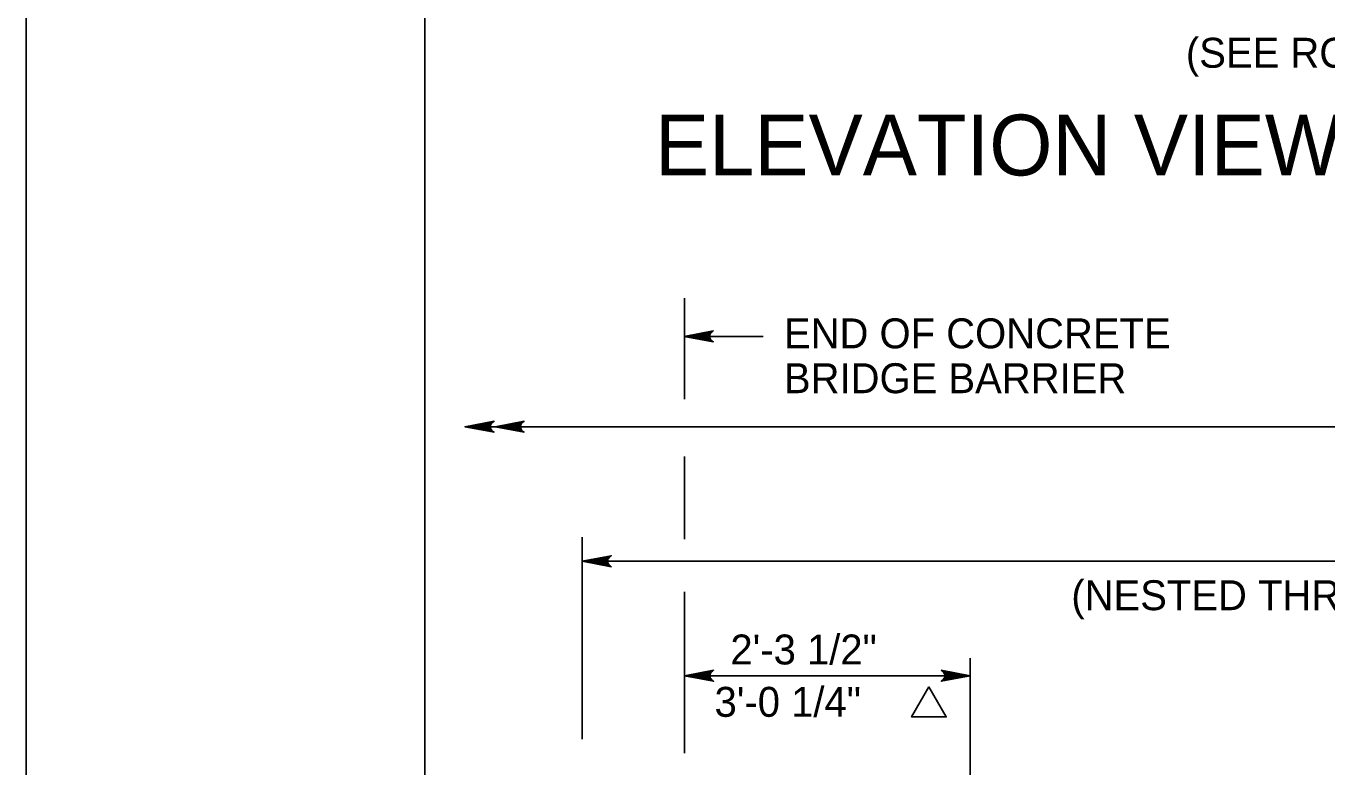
# Model space of a CAD drawing. Extents: x 632007860 to 635435983, y 295418622 to 297794622.
# Drawn here: x 632007860 to 632138300, y 297394420 to 297468725 of the extents above; entities that cross this region are included whole.
import ezdxf

# ---------------------------------------------------------------- set-up
doc = ezdxf.new("R2010")
doc.units = 0
for name, color, linetype in [('1', 7, 'Continuous'), ('2', 7, 'Continuous'), ('PLT-BNDY', 7, 'Continuous'), ('S-DETL-DIMS', 7, 'Continuous'), ('S-DETL-T120', 7, 'Continuous'), ('S-DETL-T175', 7, 'Continuous')]:
    doc.layers.add(name, color=color, linetype=linetype)

msp = doc.modelspace()

# ---------------------------------------------------------------- linework, layer by layer
at = {"layer": '1'}
msp.add_lwpolyline([(632833860, 297215622), (632833860, 297779622), (632047860, 297779622), (632047860, 297215622), (632833860, 297215622), (632833860, 297241981), (632633860, 297241981), (632633860, 297306659), (632833860, 297306659), (632833860, 297335622), (632633860, 297335622), (632633860, 297215622), (632712661, 297215622), (632712661, 297241981), (632712661, 297215622), (632789661, 297215622), (632789661, 297241981), (632789661, 297229665), (632833860, 297229665)], dxfattribs=at)
at = {"layer": '2'}
msp.add_line((632102529, 297350888), (632102529, 297405345), dxfattribs=at)
at = {"layer": 'PLT-BNDY'}
msp.add_lwpolyline([(632007860, 297794622), (632848860, 297794622), (632848860, 297200622), (632007860, 297200622)], close=True, dxfattribs=at)
at = {"layer": 'S-DETL-DIMS'}
for p, q in [((632073885, 297431304), (632073885, 297441422)), ((632081757, 297437605), (632073851, 297437605)), ((632051871, 297428546), (632532195, 297428546)), ((632073885, 297417265), (632073885, 297425550)), ((632063630, 297397221), (632063630, 297417473)), ((632063630, 297415051), (632529656, 297415051)), ((632073885, 297395818), (632073885, 297411972)), ((632073885, 297403570), (632102367, 297403570))]:
    msp.add_line(p, q, dxfattribs=at)
for points in [[(632073851, 297437605), (632076764, 297438151), (632076652, 297438073), (632076539, 297437995), (632076481, 297437898), (632076424, 297437800), (632076407, 297437702), (632076390, 297437605), (632076407, 297437507), (632076424, 297437409), (632076481, 297437312), (632076539, 297437214), (632076652, 297437136), (632076764, 297437059), (632073851, 297437605), (632076652, 297437136), (632076539, 297437214), (632073851, 297437605), (632076481, 297437312), (632076424, 297437409), (632073851, 297437605), (632076407, 297437507), (632076390, 297437605), (632073851, 297437605), (632076407, 297437702), (632076424, 297437800), (632073851, 297437605), (632076481, 297437898), (632076539, 297437995), (632073851, 297437605), (632076652, 297438073)], [(632051871, 297428546), (632054784, 297429092), (632054672, 297429014), (632054560, 297428937), (632054502, 297428839), (632054444, 297428741), (632054427, 297428644), (632054410, 297428546), (632054427, 297428448), (632054444, 297428351), (632054502, 297428253), (632054560, 297428155), (632054672, 297428078), (632054784, 297428000), (632051871, 297428546), (632054672, 297428078), (632054560, 297428155), (632051871, 297428546), (632054502, 297428253), (632054444, 297428351), (632051871, 297428546), (632054427, 297428448), (632054410, 297428546), (632051871, 297428546), (632054427, 297428644), (632054444, 297428741), (632051871, 297428546), (632054502, 297428839), (632054560, 297428937), (632051871, 297428546), (632054672, 297429014)], [(632054887, 297428546), (632057800, 297429092), (632057688, 297429014), (632057575, 297428937), (632057517, 297428839), (632057460, 297428741), (632057443, 297428644), (632057426, 297428546), (632057443, 297428448), (632057460, 297428351), (632057517, 297428253), (632057575, 297428155), (632057688, 297428078), (632057800, 297428000), (632054887, 297428546), (632057688, 297428078), (632057575, 297428155), (632054887, 297428546), (632057517, 297428253), (632057460, 297428351), (632054887, 297428546), (632057443, 297428448), (632057426, 297428546), (632054887, 297428546), (632057443, 297428644), (632057460, 297428741), (632054887, 297428546), (632057517, 297428839), (632057575, 297428937), (632054887, 297428546), (632057688, 297429014)], [(632063630, 297415051), (632066543, 297415597), (632066430, 297415519), (632066318, 297415441), (632066260, 297415344), (632066202, 297415246), (632066186, 297415148), (632066169, 297415051), (632066186, 297414953), (632066202, 297414855), (632066260, 297414758), (632066318, 297414660), (632066430, 297414582), (632066543, 297414505), (632063630, 297415051), (632066430, 297414582), (632066318, 297414660), (632063630, 297415051), (632066260, 297414758), (632066202, 297414855), (632063630, 297415051), (632066186, 297414953), (632066169, 297415051), (632063630, 297415051), (632066186, 297415148), (632066202, 297415246), (632063630, 297415051), (632066260, 297415344), (632066318, 297415441), (632063630, 297415051), (632066430, 297415519)], [(632073884, 297403570), (632076797, 297403024), (632076685, 297403102), (632076572, 297403180), (632076515, 297403277), (632076457, 297403375), (632076440, 297403473), (632076423, 297403570), (632076440, 297403668), (632076457, 297403766), (632076515, 297403863), (632076572, 297403961), (632076685, 297404039), (632076797, 297404116), (632073884, 297403570), (632076685, 297404039), (632076572, 297403961), (632073884, 297403570), (632076515, 297403863), (632076457, 297403766), (632073884, 297403570), (632076440, 297403668), (632076423, 297403570), (632073884, 297403570), (632076440, 297403473), (632076457, 297403375), (632073884, 297403570), (632076515, 297403277), (632076572, 297403180), (632073884, 297403570), (632076685, 297403102)], [(632102529, 297403570), (632099617, 297403024), (632099729, 297403102), (632099841, 297403180), (632099899, 297403277), (632099957, 297403375), (632099974, 297403473), (632099990, 297403570), (632099974, 297403668), (632099957, 297403766), (632099899, 297403863), (632099841, 297403961), (632099729, 297404039), (632099617, 297404116), (632102529, 297403570), (632099729, 297404039), (632099841, 297403961), (632102529, 297403570), (632099899, 297403863), (632099957, 297403766), (632102529, 297403570), (632099974, 297403668), (632099990, 297403570), (632102529, 297403570), (632099974, 297403473), (632099957, 297403375), (632102529, 297403570), (632099899, 297403277), (632099841, 297403180), (632102529, 297403570), (632099729, 297403102)]]:
    msp.add_lwpolyline(points, dxfattribs=at)
at = {"layer": 'S-DETL-T120'}
msp.add_lwpolyline([(632098390, 297402448), (632096658, 297399448), (632100122, 297399448)], close=True, dxfattribs=at)

# ---------------------------------------------------------------- texts
for s, height, p in [('(SEE RC-64M)', 2999.91, (632124154, 297464542)), ('END OF CONCRETE ', 2999.91, (632083851, 297436406)), ('BRIDGE BARRIER', 2999.91, (632083851, 297431906)), ('(NESTED THRIE-BEAM RAIL ELEMENTS)', 2999.85, (632112665, 297410145)), ('2\'-3 1/2"', 2999.8, (632078485, 297404703)), ('3\'-0 1/4" ', 2999.8, (632076895, 297399453))]:
    msp.add_text(s, height=height, dxfattribs=at).set_placement(p)
at = {"layer": 'S-DETL-T175'}
msp.add_text('ELEVATION VIEW FOR THRIE-BEAM GUIDE RAIL TO BRIDGE BARRIER TRANSITION', height=6096, dxfattribs=at).set_placement((632070911, 297453742))

doc.saveas('drawing.dxf')
